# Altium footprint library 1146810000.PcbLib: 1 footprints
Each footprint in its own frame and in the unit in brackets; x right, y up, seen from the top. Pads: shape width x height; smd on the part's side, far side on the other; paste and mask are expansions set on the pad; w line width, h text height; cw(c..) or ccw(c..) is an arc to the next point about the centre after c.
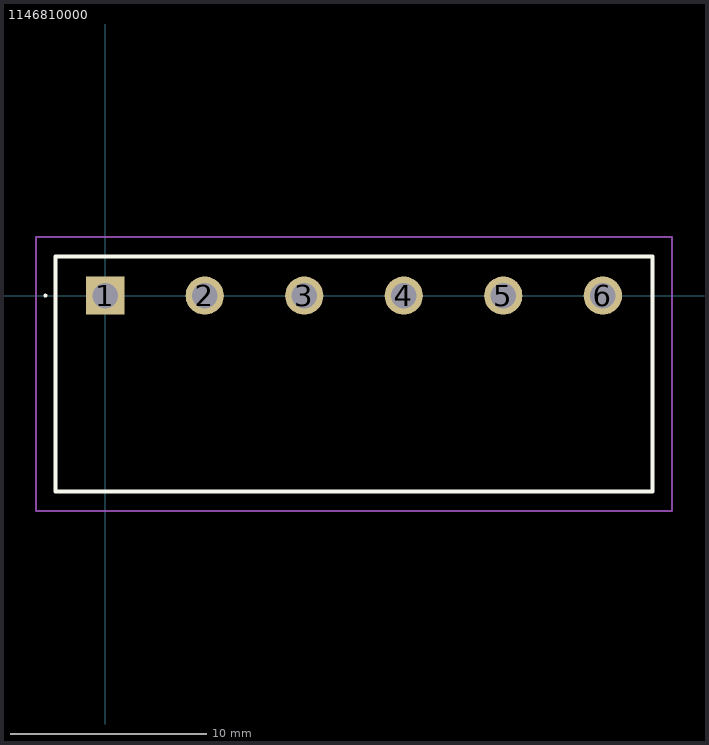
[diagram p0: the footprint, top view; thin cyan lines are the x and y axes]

## 1146810000 [mm]
pads (6):
  rect 1.95x1.95 hole 1.3: 1(0,0)
  round 1.95 hole 1.3: 2(5.08,0) 3(10.16,0) 4(15.24,0) 5(20.32,0) 6(25.4,0)
Top Overlay:
  lines w0.1: -3.1,0 cw(c-3.05,0) -3,0 ; -3.1,0 -3.1,0 ; -3.1,0 ccw(c-3.05,0) -3,0 ; -3,0 -3,0
  lines w0.2: -2.54,-10 27.94,-10 27.94,2 -2.54,2 -2.54,-10
Mechanical 15:
  lines w0.1: -2.54,-10 27.94,-10 27.94,2 -2.54,2 -2.54,-10
Mechanical 20:
  lines w0.1: -3.54,-11 28.94,-11 28.94,3 -3.54,3 -3.54,-11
